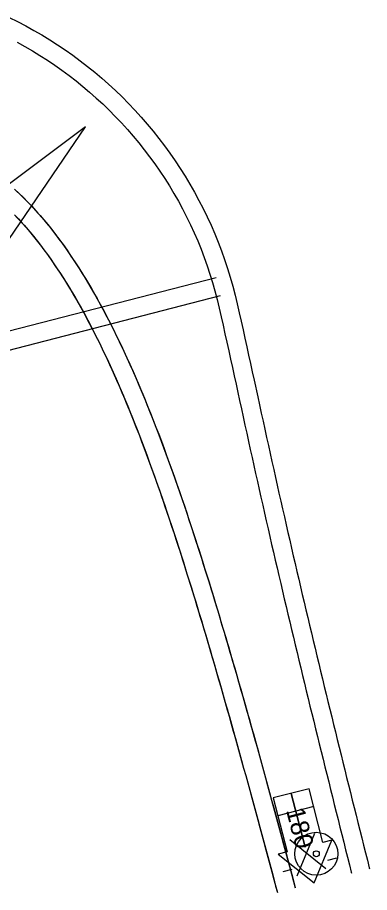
# Model space of a CAD drawing. Extents: x 916040 to 917457, y 328936 to 330267.
# Drawn here: x 916883.8 to 916921.9, y 329767.8 to 329862.4 of the extents above; entities that cross this region are included whole.
import ezdxf

# ---------------------------------------------------------------- set-up
doc = ezdxf.new("R2010")
doc.units = 0
doc.layers.add('SU_IntoDriveway', color=7, linetype='Continuous')

msp = doc.modelspace()

# ---------------------------------------------------------------- linework, layer by layer
at = {"layer": 'SU_IntoDriveway'}
for p, q in [((916820.043, 329812.325), (916905.271, 329834.298)), ((916820.542, 329810.388), (916905.77, 329832.361)), ((916915.325, 329779.06), (916911.452, 329778.059)), ((916914.89, 329772.751), (916913.388, 329778.56)), ((916913.388, 329778.56), (916914.89, 329772.751)), ((916916.826, 329773.251), (916915.325, 329779.06)), ((916911.452, 329778.059), (916912.954, 329772.25)), ((916915.825, 329777.124), (916911.953, 329776.123)), ((916914.042, 329769.639), (916915.945, 329774.263)), ((916913.234, 329773.562), (916917.14, 329770.44)), ((916915.891, 329768.878), (916917.795, 329773.501)), ((916917.795, 329773.501), (916916.826, 329773.251)), ((916912.954, 329772.25), (916911.986, 329772)), ((916911.986, 329772), (916915.891, 329768.878)), ((916918.295, 329771.565), (916917.327, 329771.315)), ((916913.454, 329770.314), (916912.486, 329770.063))]:
    msp.add_line(p, q, dxfattribs=at)
for points in [[(916882.925, 329862.394), (916883.82, 329861.95), (916884.705, 329861.488), (916885.579, 329861.005), (916886.442, 329860.504), (916887.295, 329859.984), (916888.135, 329859.446), (916888.964, 329858.889), (916889.781, 329858.314), (916890.584, 329857.721), (916891.374, 329857.111), (916892.151, 329856.484), (916892.914, 329855.84), (916893.662, 329855.179), (916894.396, 329854.502), (916895.115, 329853.809), (916895.819, 329853.101), (916896.506, 329852.377), (916897.178, 329851.638), (916897.833, 329850.885), (916898.472, 329850.118), (916899.094, 329849.336), (916899.698, 329848.542), (916900.285, 329847.734), (916900.854, 329846.914), (916901.405, 329846.081), (916901.938, 329845.236), (916902.451, 329844.38), (916902.946, 329843.513), (916903.422, 329842.635), (916903.879, 329841.747), (916904.316, 329840.85), (916904.733, 329839.943), (916905.13, 329839.027), (916905.507, 329838.102), (916905.863, 329837.169), (916906.199, 329836.229), (916906.515, 329835.282), (916906.809, 329834.328), (916907.083, 329833.368), (916907.335, 329832.402), (916907.564, 329831.44), (916907.776, 329830.498), (916907.984, 329829.571), (916908.189, 329828.648), (916908.392, 329827.73), (916908.593, 329826.816), (916908.793, 329825.907), (916908.991, 329825.002), (916909.188, 329824.101), (916909.383, 329823.204), (916909.772, 329821.422), (916909.965, 329820.536), (916910.158, 329819.653), (916910.35, 329818.774), (916910.542, 329817.898), (916910.734, 329817.025), (916910.926, 329816.155), (916911.117, 329815.288), (916911.308, 329814.424), (916911.5, 329813.562), (916911.691, 329812.702), (916911.883, 329811.845), (916912.075, 329810.99), (916912.267, 329810.137), (916912.459, 329809.286), (916912.652, 329808.437), (916912.845, 329807.59), (916913.038, 329806.745), (916913.231, 329805.902), (916913.425, 329805.06), (916913.619, 329804.22), (916913.813, 329803.381), (916914.008, 329802.543), (916914.203, 329801.707), (916914.398, 329800.872), (916914.594, 329800.039), (916914.79, 329799.206), (916914.987, 329798.375), (916915.184, 329797.545), (916915.381, 329796.715), (916915.578, 329795.887), (916915.776, 329795.06), (916915.974, 329794.233), (916916.172, 329793.408), (916916.371, 329792.583), (916916.57, 329791.759), (916916.77, 329790.935), (916916.969, 329790.113), (916917.169, 329789.291), (916917.369, 329788.47), (916917.57, 329787.649), (916917.771, 329786.829), (916917.972, 329786.009), (916918.173, 329785.19), (916918.374, 329784.372), (916918.576, 329783.554), (916918.778, 329782.736), (916918.98, 329781.919), (916919.183, 329781.102), (916919.385, 329780.286), (916919.588, 329779.47), (916919.791, 329778.655), (916919.994, 329777.84), (916920.198, 329777.025), (916920.401, 329776.21), (916920.605, 329775.396), (916920.809, 329774.582), (916921.013, 329773.769), (916921.217, 329772.956), (916921.422, 329772.143), (916921.626, 329771.33), (916921.831, 329770.517), (916921.858, 329770.408)], [(916883.758, 329859.726), (916884.594, 329859.265), (916885.42, 329858.785), (916886.234, 329858.288), (916887.038, 329857.773), (916887.831, 329857.241), (916888.611, 329856.692), (916889.379, 329856.125), (916890.135, 329855.542), (916890.878, 329854.942), (916891.607, 329854.326), (916892.322, 329853.694), (916893.024, 329853.047), (916893.711, 329852.385), (916894.384, 329851.707), (916895.041, 329851.015), (916895.684, 329850.309), (916896.31, 329849.589), (916896.921, 329848.855), (916897.515, 329848.108), (916898.093, 329847.348), (916898.654, 329846.576), (916899.198, 329845.792), (916899.725, 329844.996), (916900.234, 329844.188), (916900.725, 329843.37), (916901.199, 329842.541), (916901.654, 329841.702), (916902.09, 329840.853), (916902.508, 329839.994), (916902.906, 329839.127), (916903.286, 329838.251), (916903.647, 329837.367), (916903.987, 329836.476), (916904.309, 329835.577), (916904.61, 329834.671), (916904.892, 329833.759), (916905.153, 329832.841), (916905.395, 329831.917), (916905.616, 329830.989), (916905.825, 329830.06), (916906.032, 329829.135), (916906.237, 329828.215), (916906.439, 329827.299), (916906.64, 329826.387), (916906.839, 329825.479), (916907.037, 329824.575), (916907.234, 329823.675), (916907.429, 329822.778), (916907.624, 329821.885), (916907.818, 329820.995), (916908.011, 329820.109), (916908.204, 329819.226), (916908.397, 329818.346), (916908.589, 329817.47), (916908.781, 329816.596), (916908.972, 329815.725), (916909.164, 329814.856), (916909.356, 329813.99), (916909.548, 329813.127), (916909.74, 329812.266), (916909.932, 329811.408), (916910.124, 329810.551), (916910.316, 329809.697), (916910.509, 329808.845), (916910.702, 329807.994), (916910.895, 329807.146), (916911.088, 329806.299), (916911.282, 329805.454), (916911.476, 329804.611), (916911.67, 329803.769), (916911.865, 329802.928), (916912.06, 329802.09), (916912.256, 329801.252), (916912.451, 329800.416), (916912.647, 329799.581), (916912.844, 329798.747), (916913.041, 329797.914), (916913.238, 329797.083), (916913.435, 329796.252), (916913.633, 329795.423), (916913.831, 329794.594), (916914.029, 329793.766), (916914.228, 329792.94), (916914.427, 329792.114), (916914.626, 329791.289), (916914.826, 329790.464), (916915.026, 329789.641), (916915.226, 329788.818), (916915.426, 329787.995), (916915.627, 329787.174), (916915.828, 329786.353), (916916.029, 329785.532), (916916.231, 329784.712), (916916.433, 329783.893), (916916.634, 329783.074), (916916.837, 329782.256), (916917.039, 329781.438), (916917.242, 329780.621), (916917.444, 329779.804), (916917.647, 329778.987), (916917.851, 329778.171), (916918.054, 329777.356), (916918.257, 329776.54), (916918.461, 329775.725), (916918.665, 329774.911), (916918.869, 329774.096), (916919.073, 329773.282), (916919.277, 329772.468), (916919.482, 329771.655), (916919.687, 329770.842), (916919.891, 329770.029), (916919.919, 329769.919)], [(916883.476, 329843.849), (916883.964, 329843.398), (916884.441, 329842.937), (916884.907, 329842.468), (916885.362, 329841.991), (916885.807, 329841.506), (916886.242, 329841.015), (916886.667, 329840.518), (916887.083, 329840.015), (916887.49, 329839.507), (916887.889, 329838.994), (916888.279, 329838.476), (916888.662, 329837.953), (916889.037, 329837.427), (916889.405, 329836.897), (916889.766, 329836.363), (916890.12, 329835.826), (916890.467, 329835.285), (916890.809, 329834.742), (916891.144, 329834.196), (916891.473, 329833.647), (916891.797, 329833.095), (916892.116, 329832.541), (916892.429, 329831.985), (916892.737, 329831.427), (916893.04, 329830.867), (916893.338, 329830.305), (916893.632, 329829.741), (916893.921, 329829.176), (916894.207, 329828.608), (916894.488, 329828.04), (916894.765, 329827.47), (916895.038, 329826.898), (916895.307, 329826.325), (916895.573, 329825.751), (916895.835, 329825.176), (916896.094, 329824.6), (916896.35, 329824.022), (916896.602, 329823.444), (916896.852, 329822.864), (916897.098, 329822.284), (916897.344, 329821.697), (916897.592, 329821.098), (916897.842, 329820.488), (916898.092, 329819.866), (916898.343, 329819.235), (916898.595, 329818.594), (916898.848, 329817.943), (916899.1, 329817.284), (916899.353, 329816.617), (916899.605, 329815.943), (916899.858, 329815.261), (916900.11, 329814.572), (916900.361, 329813.877), (916900.612, 329813.176), (916900.862, 329812.469), (916901.112, 329811.756), (916901.361, 329811.039), (916901.608, 329810.317), (916901.855, 329809.59), (916902.102, 329808.859), (916902.347, 329808.124), (916902.591, 329807.386), (916902.835, 329806.643), (916903.077, 329805.898), (916903.319, 329805.149), (916903.559, 329804.397), (916903.799, 329803.643), (916904.037, 329802.885), (916904.275, 329802.125), (916904.512, 329801.363), (916904.748, 329800.599), (916904.983, 329799.832), (916905.217, 329799.064), (916905.45, 329798.293), (916905.682, 329797.521), (916905.914, 329796.747), (916906.144, 329795.971), (916906.374, 329795.194), (916906.604, 329794.416), (916906.832, 329793.636), (916907.06, 329792.855), (916907.287, 329792.072), (916907.513, 329791.289), (916907.739, 329790.504), (916907.964, 329789.718), (916908.188, 329788.932), (916908.412, 329788.144), (916908.635, 329787.355), (916908.858, 329786.566), (916909.08, 329785.776), (916909.302, 329784.985), (916909.523, 329784.193), (916909.743, 329783.401), (916909.963, 329782.608), (916910.183, 329781.814), (916910.402, 329781.02), (916910.621, 329780.225), (916910.839, 329779.429), (916911.057, 329778.634), (916911.275, 329777.837), (916911.492, 329777.04), (916911.709, 329776.243), (916911.925, 329775.445), (916912.141, 329774.647), (916912.357, 329773.849), (916912.573, 329773.05), (916912.788, 329772.25), (916913.003, 329771.451), (916913.218, 329770.651), (916913.432, 329769.851), (916913.646, 329769.05), (916913.83, 329768.362)], [(916883.643, 329843.697), (916884.128, 329843.242), (916884.606, 329842.773), (916885.081, 329842.287), (916885.554, 329841.784), (916886.022, 329841.265), (916886.487, 329840.731), (916886.946, 329840.182), (916887.401, 329839.619), (916887.85, 329839.044), (916888.294, 329838.455), (916888.733, 329837.855), (916889.165, 329837.244), (916889.592, 329836.622), (916890.013, 329835.99), (916890.427, 329835.348), (916890.836, 329834.697), (916891.239, 329834.038), (916891.636, 329833.371), (916892.027, 329832.696), (916892.412, 329832.015), (916892.792, 329831.326), (916893.166, 329830.631), (916893.534, 329829.93), (916893.897, 329829.224), (916894.255, 329828.512), (916894.607, 329827.795), (916894.955, 329827.073), (916895.297, 329826.347), (916895.635, 329825.616), (916895.968, 329824.882), (916896.296, 329824.144), (916896.62, 329823.402), (916896.94, 329822.657), (916897.256, 329821.909), (916897.568, 329821.158), (916897.875, 329820.404), (916898.18, 329819.647), (916898.48, 329818.888), (916898.777, 329818.126), (916899.07, 329817.363), (916899.361, 329816.597), (916899.648, 329815.829), (916899.932, 329815.059), (916900.213, 329814.287), (916900.491, 329813.514), (916900.767, 329812.739), (916901.04, 329811.962), (916901.31, 329811.184), (916901.578, 329810.405), (916901.844, 329809.624), (916902.107, 329808.842), (916902.369, 329808.059), (916902.628, 329807.275), (916902.885, 329806.49), (916903.14, 329805.703), (916903.393, 329804.916), (916903.645, 329804.128), (916903.894, 329803.339), (916904.143, 329802.549), (916904.389, 329801.759), (916904.634, 329800.967), (916904.878, 329800.175), (916905.12, 329799.383), (916905.36, 329798.589), (916905.6, 329797.795), (916905.838, 329797.001), (916906.075, 329796.206), (916906.311, 329795.41), (916906.545, 329794.614), (916906.779, 329793.817), (916907.012, 329793.02), (916907.243, 329792.223), (916907.474, 329791.425), (916907.704, 329790.627), (916907.932, 329789.828), (916908.16, 329789.029), (916908.388, 329788.23), (916908.614, 329787.43), (916908.84, 329786.63), (916909.065, 329785.83), (916909.289, 329785.029), (916909.513, 329784.228), (916909.736, 329783.427), (916909.958, 329782.626), (916910.18, 329781.824), (916910.401, 329781.022), (916910.622, 329780.22), (916910.842, 329779.418), (916911.062, 329778.616), (916911.281, 329777.813), (916911.5, 329777.01), (916911.718, 329776.207), (916911.936, 329775.404), (916912.154, 329774.601), (916912.371, 329773.797), (916912.588, 329772.994), (916912.804, 329772.19), (916913.02, 329771.386), (916913.236, 329770.582), (916913.452, 329769.778), (916913.667, 329768.974), (916913.83, 329768.362)], [(916883.474, 329841.073), (916883.902, 329840.624), (916884.322, 329840.167), (916884.733, 329839.702), (916885.136, 329839.231), (916885.532, 329838.752), (916885.92, 329838.268), (916886.3, 329837.778), (916886.674, 329837.283), (916887.041, 329836.782), (916887.401, 329836.277), (916887.755, 329835.767), (916888.102, 329835.253), (916888.444, 329834.734), (916888.779, 329834.212), (916889.11, 329833.687), (916889.434, 329833.158), (916889.754, 329832.626), (916890.068, 329832.09), (916890.377, 329831.552), (916890.682, 329831.012), (916890.982, 329830.468), (916891.277, 329829.922), (916891.568, 329829.374), (916891.855, 329828.824), (916892.138, 329828.271), (916892.417, 329827.716), (916892.692, 329827.16), (916892.963, 329826.601), (916893.231, 329826.041), (916893.495, 329825.48), (916893.756, 329824.916), (916894.013, 329824.351), (916894.268, 329823.785), (916894.519, 329823.217), (916894.767, 329822.648), (916895.013, 329822.078), (916895.256, 329821.507), (916895.498, 329820.928), (916895.742, 329820.338), (916895.988, 329819.736), (916896.235, 329819.123), (916896.483, 329818.499), (916896.732, 329817.866), (916896.982, 329817.223), (916897.231, 329816.572), (916897.481, 329815.913), (916897.731, 329815.245), (916897.981, 329814.57), (916898.23, 329813.888), (916898.479, 329813.2), (916898.728, 329812.505), (916898.976, 329811.804), (916899.223, 329811.098), (916899.47, 329810.387), (916899.716, 329809.67), (916899.961, 329808.949), (916900.205, 329808.224), (916900.449, 329807.494), (916900.692, 329806.76), (916900.933, 329806.023), (916901.174, 329805.282), (916901.414, 329804.537), (916901.653, 329803.79), (916901.892, 329803.039), (916902.129, 329802.286), (916902.366, 329801.53), (916902.601, 329800.772), (916902.836, 329800.011), (916903.07, 329799.248), (916903.303, 329798.483), (916903.535, 329797.715), (916903.767, 329796.946), (916903.997, 329796.175), (916904.227, 329795.403), (916904.456, 329794.628), (916904.685, 329793.852), (916904.912, 329793.075), (916905.139, 329792.296), (916905.366, 329791.516), (916905.591, 329790.735), (916905.816, 329789.952), (916906.041, 329789.169), (916906.265, 329788.384), (916906.488, 329787.598), (916906.711, 329786.812), (916906.933, 329786.024), (916907.154, 329785.235), (916907.375, 329784.446), (916907.596, 329783.656), (916907.816, 329782.865), (916908.036, 329782.074), (916908.255, 329781.281), (916908.474, 329780.488), (916908.692, 329779.695), (916908.91, 329778.901), (916909.128, 329778.106), (916909.345, 329777.311), (916909.562, 329776.515), (916909.779, 329775.719), (916909.995, 329774.922), (916910.211, 329774.125), (916910.426, 329773.327), (916910.642, 329772.529), (916910.857, 329771.731), (916911.072, 329770.932), (916911.286, 329770.133), (916911.5, 329769.333), (916911.714, 329768.534), (916911.898, 329767.845)], [(916883.637, 329840.903), (916884.082, 329840.429), (916884.525, 329839.939), (916884.965, 329839.433), (916885.402, 329838.911), (916885.835, 329838.376), (916886.264, 329837.826), (916886.688, 329837.263), (916887.109, 329836.688), (916887.524, 329836.1), (916887.935, 329835.502), (916888.34, 329834.892), (916888.741, 329834.273), (916889.136, 329833.644), (916889.526, 329833.005), (916889.911, 329832.358), (916890.291, 329831.703), (916890.666, 329831.04), (916891.035, 329830.37), (916891.4, 329829.692), (916891.759, 329829.008), (916892.114, 329828.318), (916892.464, 329827.622), (916892.809, 329826.92), (916893.149, 329826.213), (916893.485, 329825.501), (916893.816, 329824.784), (916894.143, 329824.063), (916894.466, 329823.337), (916894.785, 329822.607), (916895.1, 329821.874), (916895.411, 329821.137), (916895.718, 329820.397), (916896.022, 329819.653), (916896.322, 329818.906), (916896.618, 329818.157), (916896.912, 329817.404), (916897.202, 329816.649), (916897.489, 329815.892), (916897.773, 329815.132), (916898.054, 329814.37), (916898.333, 329813.606), (916898.608, 329812.84), (916898.881, 329812.072), (916899.152, 329811.302), (916899.42, 329810.531), (916899.686, 329809.757), (916899.95, 329808.983), (916900.211, 329808.207), (916900.47, 329807.429), (916900.728, 329806.65), (916900.983, 329805.87), (916901.237, 329805.088), (916901.489, 329804.306), (916901.739, 329803.522), (916901.987, 329802.738), (916902.234, 329801.952), (916902.479, 329801.165), (916902.723, 329800.378), (916902.965, 329799.589), (916903.206, 329798.8), (916903.446, 329798.01), (916903.685, 329797.219), (916903.922, 329796.428), (916904.158, 329795.636), (916904.393, 329794.843), (916904.627, 329794.05), (916904.859, 329793.256), (916905.091, 329792.461), (916905.322, 329791.666), (916905.552, 329790.871), (916905.781, 329790.075), (916906.01, 329789.278), (916906.237, 329788.481), (916906.464, 329787.684), (916906.69, 329786.886), (916906.915, 329786.088), (916907.139, 329785.289), (916907.363, 329784.49), (916907.586, 329783.691), (916907.809, 329782.892), (916908.031, 329782.092), (916908.252, 329781.292), (916908.473, 329780.491), (916908.694, 329779.69), (916908.914, 329778.889), (916909.133, 329778.088), (916909.352, 329777.287), (916909.57, 329776.485), (916909.788, 329775.683), (916910.006, 329774.881), (916910.223, 329774.078), (916910.44, 329773.276), (916910.657, 329772.473), (916910.873, 329771.67), (916911.089, 329770.867), (916911.305, 329770.064), (916911.52, 329769.261), (916911.735, 329768.457), (916911.898, 329767.845)]]:
    msp.add_lwpolyline(points, dxfattribs=at)
msp.add_lwpolyline([(916891.164, 329850.579), (916877.705, 329840.534), (916881.69, 329836.712)], close=True, dxfattribs=at)
for radius in [2.32, 0.32]:
    msp.add_circle((916916.109, 329772.033), radius, dxfattribs=at)

# ---------------------------------------------------------------- texts
msp.add_text('180', height=2, rotation=284.49568, dxfattribs=at).set_placement((916912.825, 329776.742))

doc.saveas('drawing.dxf')
